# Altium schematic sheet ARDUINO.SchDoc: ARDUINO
size A4; Date: Not used; ApprovedBy: Not used; CheckedBy: Not used; Author: Not used; CompanyName: STMicroelectronics; DrawnBy: Not used; Engineer: Not used; Organization: Not used; Address1: Not used; Address2: Not used; Address3: Not used; Address4: Not used; DocumentNumber: 8; Revision: Not used; SheetNumber: 8; SheetTotal: 16
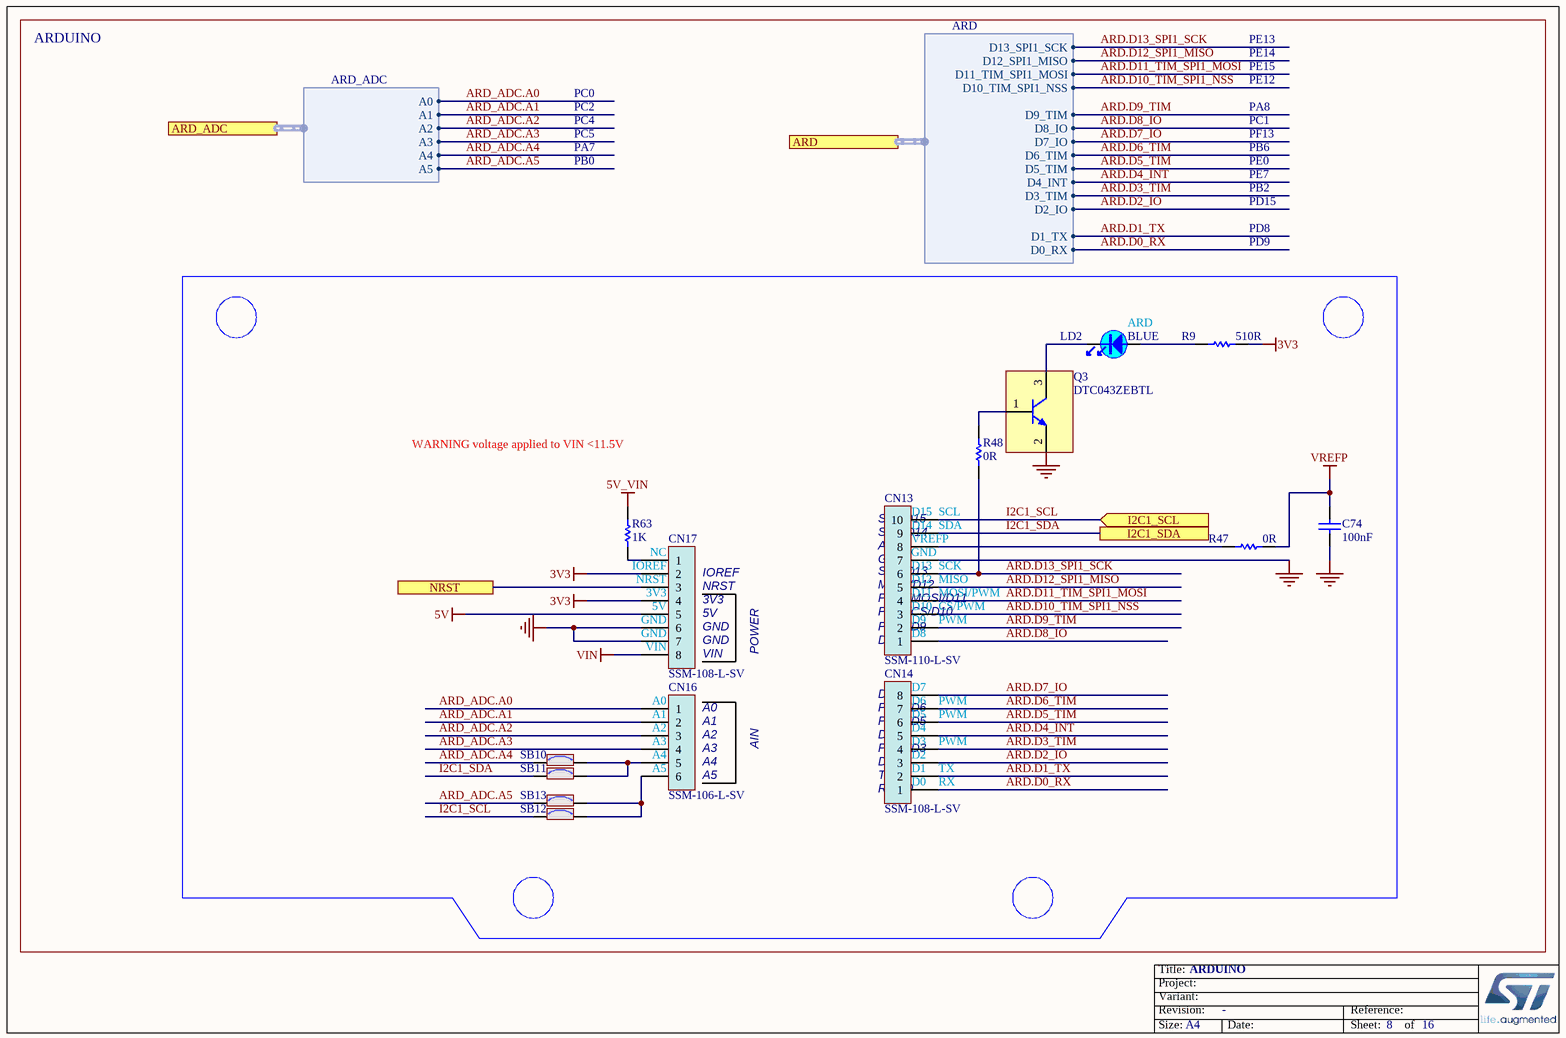
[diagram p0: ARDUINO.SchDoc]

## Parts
C74  value 100nF  [C0402]
CN13  value SSM-110-L-SV  [CON_SAMTEC_SSM-110-L-SV]  (hidden comment: Socket 10x1)
CN14  value SSM-108-L-SV  [CON_SAMTEC_SSM-108-L-SV]  (hidden comment: Socket 8x1)
CN16  value SSM-106-L-SV  [CON_SAMTEC_SSM-106-L-SV]  (hidden comment: Socket 6x1)
CN17  value SSM-108-L-SV  [CON_SAMTEC_SSM-108-L-SV]  (hidden comment: Socket 8x1)
LD2  value BLUE  [LED_0603_SMD-B_BLUE_H0P4]  (hidden comment: ​reference from jiubaba)
Q3  DTC043ZEBTL  [NPN_SOT416-FL_EMT3F_1616_SC89]
R9  value 510R  [R0402]  (hidden comment: Resistor)
R47  value 0R  [R0402]
R48  value 0R  [R0402]
R63  value 1K  [R0402]  (hidden comment: Resistor)
SB10  (no value)  [SOLDER-BRIDGE_R0603-0R]
SB11  (no value)  [SOLDER-BRIDGE_R0603-0R]
SB12  (no value)  [SOLDER-BRIDGE_R0603-0R]
SB13  (no value)  [SOLDER-BRIDGE_R0603-0R]

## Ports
ARD (harness ARD), ARD_ADC (harness ARD_ADC), I2C1_SCL (in), I2C1_SDA, NRST

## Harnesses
ARD: D0_RX, D1_TX, D2_IO, D3_TIM, D4_INT, D5_TIM, D6_TIM, D7_IO, D8_IO, D9_TIM, D10_TIM_SPI1_NSS, D11_TIM_SPI1_MOSI, D12_SPI1_MISO, D13_SPI1_SCK
ARD_ADC: A0, A1, A2, A3, A4, A5

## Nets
3V3: CN17.2 CN17.4 R9.1
5V: CN17.5
5V_VIN: R63.2
GND: C74.2 CN13.7 CN17.6 CN17.7 Q3.2(E)
VIN: CN17.8
VREFP: C74.1 R47.2
ARD.D0_RX: CN14.1 ; port ARD.D0_RX
ARD.D1_TX: CN14.2 ; port ARD.D1_TX
ARD.D2_IO: CN14.3 ; port ARD.D2_IO
ARD.D3_TIM: CN14.4 ; port ARD.D3_TIM
ARD.D4_INT: CN14.5 ; port ARD.D4_INT
ARD.D5_TIM: CN14.6 ; port ARD.D5_TIM
ARD.D6_TIM: CN14.7 ; port ARD.D6_TIM
ARD.D7_IO: CN14.8 ; port ARD.D7_IO
ARD.D8_IO: CN13.1 ; port ARD.D8_IO
ARD.D9_TIM: CN13.2 ; port ARD.D9_TIM
ARD.D10_TIM_SPI1_NSS: CN13.3 ; port ARD.D10_TIM_SPI1_NSS
ARD.D11_TIM_SPI1_MOSI: CN13.4 ; port ARD.D11_TIM_SPI1_MOSI
ARD.D12_SPI1_MISO: CN13.5 ; port ARD.D12_SPI1_MISO
ARD.D13_SPI1_SCK: CN13.6 R48.1 ; port ARD.D13_SPI1_SCK
ARD_ADC.A0: CN16.1 ; port ARD_ADC.A0
ARD_ADC.A1: CN16.2 ; port ARD_ADC.A1
ARD_ADC.A2: CN16.3 ; port ARD_ADC.A2
ARD_ADC.A3: CN16.4 ; port ARD_ADC.A3
ARD_ADC.A4: SB10.1 ; port ARD_ADC.A4
ARD_ADC.A5: SB13.1 ; port ARD_ADC.A5
I2C1_SCL: CN13.10 SB12.1 ; port I2C1_SCL
I2C1_SDA: CN13.9 SB11.1 ; port I2C1_SDA
NRST: CN17.3 ; port NRST
NetCN13_8: CN13.8 R47.1
NetCN16_5: CN16.5 SB10.2 SB11.2
NetCN16_6: CN16.6 SB12.2 SB13.2
NetCN17_1: CN17.1 R63.1
NetLD2_1: LD2.1 R9.2
NetLD2_2: LD2.2 Q3.3(C)
NetQ3_1: Q3.1(B) R48.2

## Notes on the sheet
- ARDUINO
- PE13
- PC2
- PC0
- PA8
- PE15
- PE12
- PE14
- PC5
- PA7
- PC4
- PB0
- PE0
- PB6
- PE7
- PC1
- PF13
- PD8
- PD9
- PB2
- PD15
- (near LD2) ARD
- WARNING voltage applied to VIN <11.5V
- (near CN13) SCL/D15
- (near CN13) D15
- (near CN13) SCL
- (near CN17) NC
- (near CN17) IOREF
- (near CN17) NRST
- (near CN13) SDA/D14
- (near CN13) SCK/D13
- (near CN13) MISO/D12
- (near CN13) AVDD
- (near CN13) GND
- (near CN13) VREFP
- (near CN13) D12
- (near CN13) D13
- (near CN13) D14
- (near CN13) SDA
- (near CN13) SCK
- (near CN13) MISO
- (near CN17) 3V3
- (near CN17) 5V
- (near CN17) GND
- (near CN17) VIN
- POWER
- (near CN13) D8
- (near CN13) PWM/D9
- (near CN13) PWM/CS/D10
- (near CN13) PWM/MOSI/D11
- (near CN13) D9
- (near CN13) D10
- (near CN13) D11
- (near CN13) MOSI/PWM
- (near CN13) CS/PWM
- (near CN13) PWM
- (near CN16) A0
- (near CN16) A1
- (near CN14) PWM/D6
- (near CN14) D7
- (near CN14) D6
- (near CN14) D5
- (near CN14) PWM
- (near CN16) A2
- (near CN16) A3
- (near CN16) A4
- (near CN16) A5
- AIN
- (near CN14) RX/D0
- (near CN14) TX/D1
- (near CN14) D2
- (near CN14) D4
- (near CN14) PWM/D3
- (near CN14) PWM/D5
- (near CN14) D3
- (near CN14) D1
- (near CN14) D0
- (near CN14) TX
- (near CN14) RX

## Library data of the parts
C74 = MCD-00006: Capacitor,100nF,16V,X7R,10%,0402; Manufacturer_Part_Number: CC0402KRX7R7BB104; Manufacturer: YAGEO; Provided_By: Subcon; Initial_Board_Reference: mb1274
CN13 = MCD-02342: Socket, 10x1, 2.54mm, VR, SMT, Height 7.37mm; Part_Type: Connector; Part_Preference: Recommended; Manufacturer: SAMTEC; Order_Code_RS: 765-5420
CN14 CN17 = MCD-02345: Socket, 8x1, 2.54mm, VR, SMT, Height 7.37mm; Part_Type: Connector; Part_Preference: Recommended; Manufacturer: SAMTEC; Order_Code_RS: 765-5411
CN16 = MCD-02346: Socket, 6x1, 2.54mm, VR, SMT, Height 7.37mm; Part_Type: Connector; Part_Preference: Recommended; Manufacturer: SAMTEC; Order_Code_RS: 765-5408
LD2 = MCD-01131: LED Blue, 0603 SMD, Forward Voltage Min=2,8V, Max=3,1V; Part_Type: Display; Manufacturer_Part_Number: 19-217-BHC-ZL1M2RY-3T; Manufacturer: EVERLIGHT; Provided_By: Subcon; Initial_Board_Reference: MB1272
Q3 = MCD-00280: Buffer transistor; Part_Type: IC; Manufacturer: ROHM; Provided_By: Subcon; Initial_Board_Reference: MB1329
R9 = MCD-00064: Resistor,510R,0402,1%,1/16W; Manufacturer_Part_Number: RC0402FR-07510RL; Manufacturer: YAGEO; Provided_By: Subcon; Initial_Board_Reference: MB1274
R47 R48 = MCD-00052: Resistor,0R,0402,5%,1/16W; Manufacturer_Part_Number: RC0402JR-070RL; Manufacturer: YAGEO; Provided_By: Subcon; Initial_Board_Reference: mb1274
R63 = MCD-00061: Resistor,1K,0402,1%,1/16W; Manufacturer_Part_Number: RC0402FR-071KL; Manufacturer: YAGEO; Provided_By: Subcon; Initial_Board_Reference: mb1274
SB10-SB13 = MCD-00071: Solder Bridge ON; Part_Type: Mechanical; Provided_By: Subcon; Initial_Board_Reference: mb1274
